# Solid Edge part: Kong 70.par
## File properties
Title: Kong 70 70x39 Cm
Author: DESYS
Template: Normal.par
Last saved by: s.pallini
Revision: 12
Application: Solid Edge
Tipo di contenuto documento: 0
Precisione: 0,990
Document Number: 8052
Revision: 0
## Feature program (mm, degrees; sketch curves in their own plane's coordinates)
thicken "Assegnare_spessore_2"  Distance1 = 10 mm
thicken "Assegnare_spessore_1"  Distance1 = 10 mm
fillet "Rotondo_1" radius 30
fillet "Rotondo_2" radius 5
fillet "Rotondo_3" radius 5
sketch for "unnamed Cutout 1" plane through (0, 0, 0) normal (0, 0, 1) x-axis (1, 0, 0)
  circle centre (0, 0) radius 25
extrude "unnamed Cutout 1" cut through
sketch for "ExtrudedProtrusion_1" plane through (0, 0, 25) normal (0, 0, 1) x-axis (1, 0, 0)
extrude "ExtrudedProtrusion_1" add  Profile_Plane1_Distance = 25 mm
fillet "Rotondo_4" radius 10
sketch for "ExtrudedCutout_2" #1 plane through (0.4335, 0, 25) normal (0, 0, -1) x-axis (0, -1, 0)
sketch for "ExtrudedCutout_2" #2 plane through (0.4335, 0, 25) normal (0, 0, -1) x-axis (0, -1, 0)
extrude "ExtrudedCutout_2" cut finite 15 along -normal
fillet "Rotondo_5" radius 5
sketch for "unnamed Cutout 2" plane through (0, 0, 25) normal (0, 0, -1) x-axis (0, 1, 0)
  arc centre (0, 0) radius 25 from (-2.1303, -24.9091) to (24.1476, 6.4726) cw
  arc centre (0, 0) radius 25 from (24.1476, 6.4726) to (-2.1303, -24.9091) cw
extrude "unnamed Cutout 2" cut through along -normal
Other named dimensions: "CurveByTable_2": Tolerance = 1 mm | "CurveByTable_3": Tolerance = 1 mm | "CurveByTable_4": Tolerance = 1 mm
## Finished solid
Body 1: solid body, 31 faces, 57 edges, 28 vertices.
  Faces by surface: blend 21, plane 3, cylinder 2, swept 2, offset 1, spline 1, torus 1
  Edges by curve: intersection 36, circle 20, ellipse 1
Body 2: sheet body, 1 face, 4 edges, 4 vertices.
  Faces by surface: spline 1
  Edges by curve: spline 4
Bounding box of the edges (mm; curved faces can reach further): 374.063 x 730.000 x 122.976, from (-190.6216, -370, 25) to (183.4413, 360, 147.9764).
Cylindrical faces by radius (mm): R25 x1, R35 x1
Toroidal faces (ring radius, tube radius in mm): R30 r5 x1
Planar faces by outward normal: -z 3
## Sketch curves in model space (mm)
arc centre (-31.4438, 0, 329.9271) radius 287.5849 from (-190, 0, 90) through (3.2769, 0, 44.4458) to (180, 0, 135)
circle centre (0, 0, 20) radius 25
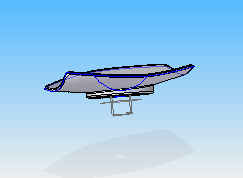
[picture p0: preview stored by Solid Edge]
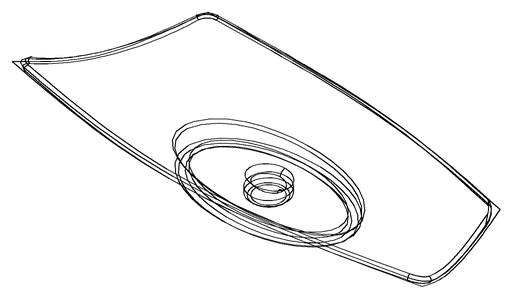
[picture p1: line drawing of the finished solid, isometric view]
